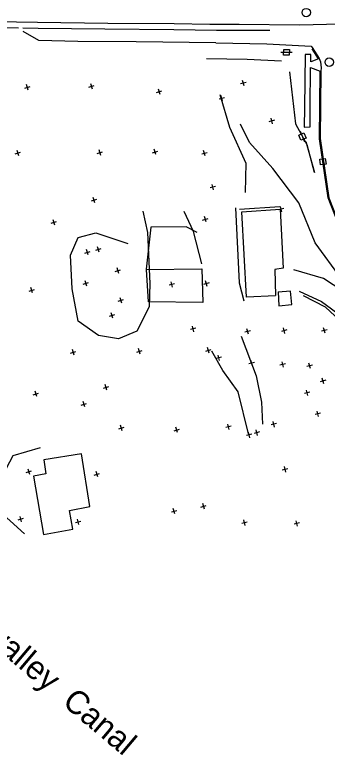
# Model space of a CAD drawing. Extents: x 4711259 to 4716401, y 890074 to 892728.
# Drawn here: x 4714101 to 4714377, y 890691 to 891346 of the extents above; entities that cross this region are included whole.
import ezdxf

# ---------------------------------------------------------------- set-up
doc = ezdxf.new("R2010")
doc.units = 0
for name, color, linetype in [('E_HY_STORM_Inlet', 7, 'Continuous'), ('E_HY_STORM_MH', 7, 'Continuous'), ('E_HY_WATER_GeneralTx', 7, 'Continuous'), ('E_RDWY_PHOTOG_Eave', 7, 'Continuous'), ('E_RDWY_PHOTOG_Fence', 7, 'Continuous'), ('E_RDWY_ROAD_Approach', 7, 'Continuous'), ('E_RDWY_ROAD_Curb', 7, 'Continuous'), ('E_RDWY_ROAD_EdgeAsph', 7, 'Continuous'), ('E_RDWY_ROAD_Sidewalk', 7, 'Continuous'), ('E_RDWY_ROAD_Striping', 7, 'Continuous'), ('E_RDWY_ROAD_TBofCurb', 7, 'Continuous'), ('E_TERR_DTM_BrkLines', 7, 'Continuous'), ('E_TERR_DTM_RandomPt', 7, 'Continuous'), ('E_UTIL_ELEC_POLE', 7, 'Continuous')]:
    doc.layers.add(name, color=color, linetype=linetype)

msp = doc.modelspace()

# ---------------------------------------------------------------- linework, layer by layer
at = {"layer": 'E_HY_STORM_Inlet'}
msp.add_line((4714373.32, 891216.11), (4714373.32, 891216.11), dxfattribs=at)
msp.add_lwpolyline([(4714376.18, 891214.04), (4714371.24, 891213.25), (4714370.46, 891218.19), (4714375.4, 891218.97)], close=True, dxfattribs=at)
at = {"layer": 'E_HY_STORM_MH'}
for centre in [(4714358.53, 891348.02), (4714378.94, 891304.16)]:
    msp.add_circle(centre, 3.75, dxfattribs=at)
at = {"layer": 'E_RDWY_PHOTOG_Eave'}
for points in [[(4714331.35, 891097.51), (4714305.65, 891096.36), (4714301.46, 891171.71), (4714335.42, 891174.05), (4714338.12, 891121.83), (4714330.6, 891120.81), (4714331.39, 891097.63)], [(4714333.67, 891100.87), (4714334.22, 891088.41), (4714345.82, 891089.61), (4714344.65, 891101.59), (4714333.75, 891100.69)], [(4714126.22, 890952.29), (4714128.07, 890939.82), (4714117.24, 890937.94), (4714126.05, 890886.32), (4714151.87, 890890.95), (4714148.93, 890907.4), (4714167.13, 890911.06), (4714159.76, 890957.61), (4714126.23, 890952.15)]]:
    msp.add_lwpolyline(points, dxfattribs=at)
at = {"layer": 'E_RDWY_PHOTOG_Fence'}
for points in [[(4714262.01, 891153.46), (4714252.23, 891158.41), (4714220.88, 891158.21), (4714216.84, 891120.96)], [(4714216.96, 891120.62), (4714266.01, 891121.29), (4714266.95, 891091.47), (4714218.96, 891092.05), (4714217.03, 891120.7)]]:
    msp.add_lwpolyline(points, dxfattribs=at)
at = {"layer": 'E_RDWY_ROAD_Approach'}
for points in [[(4714415.04, 891082.93), (4714391.04, 891101.39), (4714373.75, 891112.6), (4714347.66, 891120.54)], [(4714352.12, 891101.65), (4714371.97, 891092.43), (4714391.01, 891078.58), (4714403.8, 891064.74), (4714423.42, 891059.06)]]:
    msp.add_lwpolyline(points, dxfattribs=at)
at = {"layer": 'E_RDWY_ROAD_Curb'}
msp.add_lwpolyline([(4714362.96, 891318.22), (4714363.75, 891317.23), (4714369.9, 891307.53), (4714371.1, 891304.39), (4714371.6, 891299.06), (4714371.57, 891296.26), (4714370.89, 891236.47), (4714378.4, 891184.1), (4714400.18, 891129.64), (4714417.42, 891087.31), (4714418.62, 891084.36), (4714431.7, 891053.03), (4714432.89, 891049.43), (4714435.27, 891043.86)], dxfattribs=at)
at = {"layer": 'E_RDWY_ROAD_EdgeAsph'}
for points in [[(4713874.37, 891330.31), (4713880.32, 891335.02), (4713912.29, 891336.09), (4713970.87, 891335.69), (4714017.26, 891335.57), (4714062.02, 891335.32), (4714103.97, 891334.6)], [(4714278.54, 891321.36), (4714207.92, 891322.05), (4714156.28, 891322.58), (4714121.82, 891323.34), (4714108.12, 891331.38)], [(4714278.54, 891321.36), (4714323.76, 891320.52), (4714362.96, 891318.22)]]:
    msp.add_lwpolyline(points, dxfattribs=at)
at = {"layer": 'E_RDWY_ROAD_Sidewalk'}
msp.add_lwpolyline([(4714369.31, 891307.01), (4714362.53, 891304.53), (4714362.55, 891310.94), (4714357.5, 891310.95), (4714357.03, 891264.11), (4714356.79, 891246.77), (4714361.89, 891246.85), (4714362.03, 891263.96), (4714362.43, 891299.41), (4714370.83, 891296.2)], dxfattribs=at)
at = {"layer": 'E_RDWY_ROAD_Striping'}
for points in [[(4713887.16, 891341.3), (4713942.27, 891340.9), (4714001.89, 891340.83), (4714065.08, 891340.32), (4714120.8, 891339.62), (4714182.86, 891338.54), (4714241.54, 891338.23), (4714273.17, 891337.79)], [(4714273.17, 891337.79), (4714299.21, 891337.64), (4714352.47, 891337.17)]]:
    msp.add_lwpolyline(points, dxfattribs=at)
at = {"layer": 'E_RDWY_ROAD_TBofCurb'}
for points in [[(4714369.31, 891307.01), (4714363.85, 891316.01)], [(4714417.97, 891084.32), (4714416.83, 891086.94), (4714402.83, 891121.53), (4714392.97, 891145.9), (4714377.83, 891183.98), (4714370.12, 891236.23), (4714370.83, 891296.2)]]:
    msp.add_lwpolyline(points, dxfattribs=at)
at = {"layer": 'E_TERR_DTM_BrkLines'}
for points in [[(4714107.88, 891334.53), (4714121.39, 891334.3), (4714180.22, 891333.69), (4714241.4, 891333.07), (4714279.02, 891332.62)], [(4714279.02, 891332.62), (4714326.24, 891332.43)], [(4714352.47, 891337.17), (4714388.51, 891338.06), (4714430.85, 891335.81)], [(4714336.58, 891305.12), (4714306.26, 891306.47), (4714270.23, 891307.11)], [(4714343.62, 891295.63), (4714348.9, 891249.71), (4714358.97, 891231.27), (4714365.57, 891206.85)], [(4714281.98, 891275.52), (4714290.75, 891246.76), (4714305.11, 891214.87), (4714304.61, 891188.97)], [(4714404.3, 891099.6), (4714389.74, 891112.36), (4714366.4, 891144.37), (4714352.04, 891179.82), (4714328.87, 891210.02), (4714308.26, 891233.07), (4714300.27, 891249.27)], [(4714366.2, 891206.22), (4714358.43, 891233.78)], [(4714296.05, 891175.27), (4714299.25, 891108.89), (4714303.19, 891092.95)], [(4714299.5, 891173.98), (4714335.28, 891176.48)], [(4714213.99, 891172.18), (4714217.96, 891153.37), (4714220.04, 891108.39), (4714219.62, 891087.81), (4714208.5, 891066.27), (4714192.34, 891059.42), (4714174.69, 891062.18), (4714156.73, 891074.93), (4714151.5, 891103.71), (4714149.77, 891133.49), (4714156.79, 891148.89), (4714172.28, 891153.13), (4714200.59, 891143.85)], [(4714266.02, 891125.85), (4714258.78, 891154.31), (4714250.61, 891172.13)], [(4714405.8, 891026.88), (4714409.67, 891044.94), (4714403.38, 891060.41), (4714391.71, 891072.23), (4714375.46, 891087.37), (4714356.05, 891097.25)], [(4714300.91, 891061.77), (4714314.31, 891026.52), (4714318.82, 891003.31), (4714319.67, 890983.83)], [(4714307.34, 890975.23), (4714298.22, 891012.41), (4714284.79, 891031.19), (4714275.03, 891048.36)], [(4714109.27, 890886.86), (4714083.52, 890909.8), (4714087.06, 890933.71), (4714099.09, 890956.22), (4714123.31, 890963.15)]]:
    msp.add_lwpolyline(points, dxfattribs=at)
at = {"layer": 'E_TERR_DTM_RandomPt'}
for p, q in [((4714305.27, 891286.14), (4714300.43, 891284.89)), ((4714303.47, 891283.09), (4714302.22, 891287.94)), ((4714109.38, 891281.14), (4714114.17, 891282.59)), ((4714112.5, 891279.47), (4714111.05, 891284.26)), ((4714166.19, 891281.97), (4714170.98, 891283.41)), ((4714169.31, 891280.29), (4714167.86, 891285.08)), ((4714229.17, 891275.54), (4714227.73, 891280.32)), ((4714226.06, 891277.21), (4714230.84, 891278.65)), ((4714281.42, 891271.57), (4714286.21, 891273.02)), ((4714284.54, 891269.9), (4714283.09, 891274.69)), ((4714328.59, 891249.69), (4714327.34, 891254.54)), ((4714330.39, 891252.74), (4714325.55, 891251.49)), ((4714225.46, 891222.37), (4714224.01, 891227.15)), ((4714101.03, 891222.95), (4714105.81, 891224.4)), ((4714104.14, 891221.28), (4714102.7, 891226.07)), ((4714173.52, 891223.32), (4714178.3, 891224.77)), ((4714176.63, 891221.65), (4714175.19, 891226.44)), ((4714222.34, 891224.04), (4714227.13, 891225.48)), ((4714266.04, 891222.92), (4714270.83, 891224.37)), ((4714269.16, 891221.25), (4714267.71, 891226.04)), ((4714276.46, 891191.1), (4714275.21, 891195.94)), ((4714278.26, 891194.15), (4714273.42, 891192.9)), ((4714168.41, 891181.4), (4714173.2, 891182.85)), ((4714171.53, 891179.73), (4714170.08, 891184.52)), ((4714337.04, 891171.62), (4714335.79, 891176.46)), ((4714338.84, 891174.66), (4714334, 891173.41)), ((4714132.79, 891161.62), (4714137.58, 891163.06)), ((4714135.91, 891159.95), (4714134.46, 891164.73)), ((4714266.86, 891164.45), (4714271.65, 891165.9)), ((4714269.98, 891162.78), (4714268.53, 891167.57)), ((4714162.48, 891135.28), (4714167.26, 891136.72)), ((4714165.59, 891133.61), (4714164.15, 891138.39)), ((4714172.22, 891137.7), (4714177.01, 891139.15)), ((4714175.34, 891136.03), (4714173.9, 891140.82)), ((4714189.43, 891118.91), (4714194.22, 891120.36)), ((4714192.55, 891117.24), (4714191.1, 891122.03)), ((4714164.32, 891106.03), (4714162.87, 891110.81)), ((4714240.16, 891104.94), (4714238.91, 891109.78)), ((4714270.72, 891105.78), (4714269.46, 891110.62)), ((4714113.27, 891101.58), (4714118.05, 891103.02)), ((4714116.38, 891099.91), (4714114.94, 891104.69)), ((4714161.2, 891107.7), (4714165.99, 891109.14)), ((4714241.96, 891107.98), (4714237.12, 891106.73)), ((4714272.51, 891108.82), (4714267.67, 891107.57)), ((4714192.09, 891092.63), (4714196.88, 891094.08)), ((4714195.2, 891090.96), (4714193.76, 891095.75)), ((4714184.33, 891079.33), (4714189.12, 891080.77)), ((4714187.45, 891077.66), (4714186, 891082.45)), ((4714259.09, 891065.66), (4714257.84, 891070.5)), ((4714260.89, 891068.71), (4714256.05, 891067.46)), ((4714309.09, 891066.53), (4714304.25, 891065.28)), ((4714307.29, 891063.48), (4714306.04, 891068.32)), ((4714341.35, 891067.19), (4714336.51, 891065.94)), ((4714339.56, 891064.14), (4714338.3, 891068.98)), ((4714376.95, 891067.27), (4714372.11, 891066.02)), ((4714375.16, 891064.22), (4714373.91, 891069.06)), ((4714211.62, 891045.88), (4714210.18, 891050.67)), ((4714272.67, 891046.78), (4714271.22, 891051.57)), ((4714149.95, 891046.71), (4714154.73, 891048.15)), ((4714153.06, 891045.04), (4714151.62, 891049.82)), ((4714208.51, 891047.55), (4714213.29, 891049)), ((4714269.55, 891048.45), (4714274.34, 891049.9)), ((4714281.83, 891040.19), (4714280.58, 891045.04)), ((4714283.63, 891043.24), (4714278.79, 891041.99)), ((4714312.62, 891038.5), (4714307.78, 891037.25)), ((4714310.83, 891035.46), (4714309.58, 891040.3)), ((4714340.14, 891037.3), (4714335.3, 891036.05)), ((4714338.35, 891034.26), (4714337.1, 891039.1)), ((4714362.19, 891033.08), (4714360.94, 891037.93)), ((4714363.99, 891036.13), (4714359.15, 891034.88)), ((4714374, 891019.63), (4714372.75, 891024.47)), ((4714182.15, 891014.07), (4714180.7, 891018.86)), ((4714375.8, 891022.68), (4714370.96, 891021.43)), ((4714116.89, 891009.93), (4714121.68, 891011.38)), ((4714120.01, 891008.26), (4714118.56, 891013.05)), ((4714179.03, 891015.74), (4714183.82, 891017.19)), ((4714361.69, 891012.18), (4714356.85, 891010.93)), ((4714359.89, 891009.13), (4714358.64, 891013.97)), ((4714159.36, 891000.7), (4714164.14, 891002.14)), ((4714162.47, 890999.03), (4714161.03, 891003.82)), ((4714371.18, 890993.6), (4714366.34, 890992.34)), ((4714369.38, 890990.55), (4714368.13, 890995.39)), ((4714330.51, 890981.32), (4714329.26, 890986.16)), ((4714192.62, 890979.69), (4714197.4, 890981.13)), ((4714195.73, 890978.02), (4714194.29, 890982.81)), ((4714241.59, 890978.08), (4714246.37, 890979.53)), ((4714244.7, 890976.41), (4714243.26, 890981.2)), ((4714292.13, 890982.09), (4714287.29, 890980.84)), ((4714290.34, 890979.04), (4714289.09, 890983.88)), ((4714315.42, 890973.87), (4714314.17, 890978.71)), ((4714332.31, 890984.37), (4714327.47, 890983.12)), ((4714310.39, 890974.93), (4714305.55, 890973.68)), ((4714308.59, 890971.88), (4714307.34, 890976.72)), ((4714317.22, 890976.92), (4714312.38, 890975.67)), ((4714340.4, 890941.4), (4714339.15, 890946.24)), ((4714110.75, 890941.04), (4714115.53, 890942.49)), ((4714113.86, 890939.37), (4714112.42, 890944.16)), ((4714170.86, 890938.83), (4714175.65, 890940.27)), ((4714173.98, 890937.16), (4714172.53, 890941.94)), ((4714342.2, 890944.45), (4714337.35, 890943.2)), ((4714268.44, 890908.73), (4714267, 890913.52)), ((4714239.16, 890906.12), (4714243.95, 890907.57)), ((4714242.28, 890904.45), (4714240.83, 890909.24)), ((4714265.33, 890910.4), (4714270.11, 890911.85)), ((4714103.57, 890899.09), (4714108.36, 890900.53)), ((4714106.69, 890897.42), (4714105.24, 890902.2)), ((4714157.42, 890895.03), (4714155.98, 890899.81)), ((4714154.31, 890896.7), (4714159.09, 890898.14)), ((4714306.25, 890897.27), (4714301.41, 890896.02)), ((4714304.46, 890894.22), (4714303.21, 890899.06)), ((4714352.7, 890896.57), (4714347.86, 890895.32)), ((4714350.91, 890893.52), (4714349.66, 890898.36))]:
    msp.add_line(p, q, dxfattribs=at)
at = {"layer": 'E_UTIL_ELEC_POLE'}
for p, q in [((4714346.05, 891312.74), (4714336.05, 891312.83)), ((4714353.23, 891242.98), (4714357.12, 891233.77))]:
    msp.add_line(p, q, dxfattribs=at)
for points in [[(4714343.53, 891310.26), (4714338.53, 891310.31), (4714338.57, 891315.31), (4714343.57, 891315.26)], [(4714356.51, 891241.65), (4714358.45, 891237.04), (4714353.84, 891235.1), (4714351.9, 891239.71)]]:
    msp.add_lwpolyline(points, close=True, dxfattribs=at)

# ---------------------------------------------------------------- texts
at = {"layer": 'E_HY_WATER_GeneralTx'}
msp.add_text('Swalley  Canal', height=20.6693, rotation=319.85334, dxfattribs=at).set_placement((4714057.17, 890807.61))

doc.saveas('drawing.dxf')
